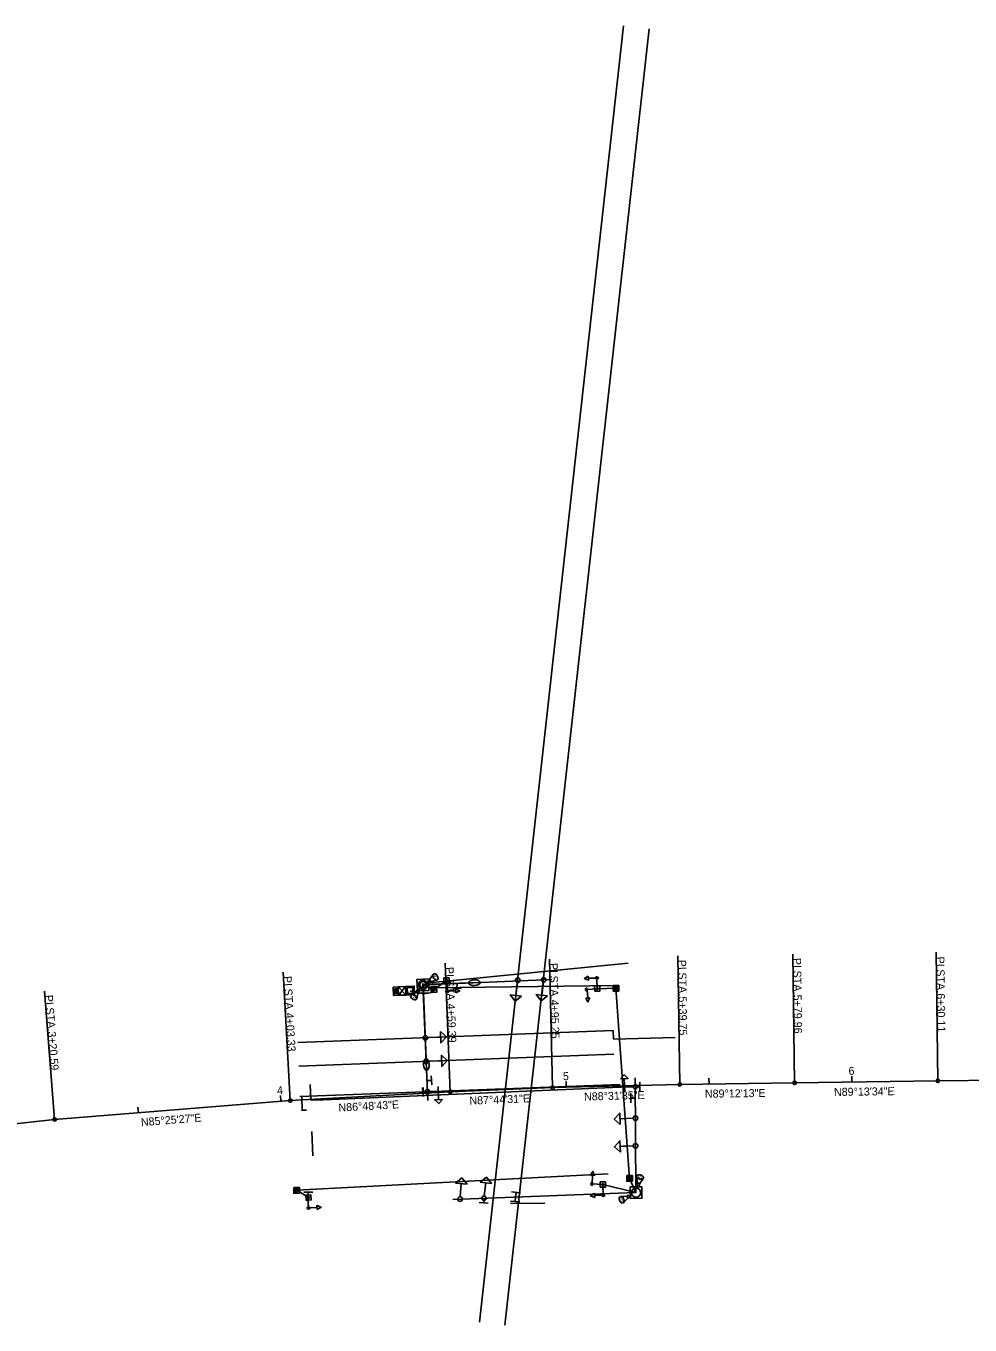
# Model space of a CAD drawing. Extents: x 1369241 to 1370511, y 405823 to 406278.
# Drawn here: x 1369555.1 to 1369885.4, y 405822.9 to 406277.6 of the extents above; entities that cross this region are included whole.
import ezdxf

# ---------------------------------------------------------------- set-up
doc = ezdxf.new("R2010")
doc.units = 0
for name, color, linetype in [('_CIVIL_CONSTRUCTION', 7, 'Continuous'), ('CM_Corridor_Conceptual', 7, 'Continuous'), ('CM_Corridor_Range_Conceptual', 7, 'Continuous'), ('DT_P_Tie', 7, 'Continuous'), ('GE_P_Alignment', 7, 'Continuous'), ('MD_P_ACB_B', 7, 'Continuous'), ('MD_P_ACIC_B', 7, 'Continuous'), ('MD_P_ACSC_T', 7, 'Continuous'), ('MD_P_CSS_B', 7, 'Continuous'), ('MD_P_CURB_BACK_BOT', 7, 'Continuous'), ('MD_P_CURB_BACK_TOP', 7, 'Continuous'), ('MD_P_CURB_FACE_TOP', 7, 'Continuous'), ('PM_P_Crosswalk', 7, 'Continuous'), ('SC_Scratch1', 7, 'Continuous')]:
    doc.layers.add(name, color=color, linetype=linetype)

msp = doc.modelspace()

# ---------------------------------------------------------------- linework, layer by layer
at = {"layer": '_CIVIL_CONSTRUCTION'}
for p, q in [((1369685.39, 405938.97), (1369684.07, 405940.53)), ((1369684.14, 405938.91), (1369685.31, 405940.59)), ((1369688.08, 405938.41), (1369685.28, 405941.28)), ((1369685.42, 405938.28), (1369687.94, 405941.4))]:
    msp.add_line(p, q, dxfattribs=at)
for points in [[(1369691.08, 405938.55), (1369690.94, 405941.54), (1369683.57, 405941.2), (1369683.71, 405938.2)], [(1369685.39, 405938.97), (1369684.14, 405938.91), (1369684.07, 405940.53), (1369685.31, 405940.59)], [(1369688.08, 405938.41), (1369685.42, 405938.28), (1369685.28, 405941.28), (1369687.94, 405941.4)], [(1369691.08, 405938.55), (1369690.94, 405941.54), (1369687.94, 405941.4), (1369688.08, 405938.41)], [(1369690.56, 405939.02), (1369690.46, 405941.02), (1369688.47, 405940.93), (1369688.56, 405938.93)]]:
    msp.add_lwpolyline(points, close=True, dxfattribs=at)
at = {"layer": 'CM_Corridor_Conceptual'}
for p, q in [((1369702.28, 405944.43), (1369702.28, 405944.43)), ((1369727.07, 405942.78), (1369726.53, 405938.22)), ((1369736.14, 405942.93), (1369735.61, 405938.37)), ((1369756.1, 405940.72), (1369756.1, 405940.72)), ((1369755.03, 405939.65), (1369755.03, 405939.65)), ((1369695.61, 405923.5), (1369700.21, 405923.67)), ((1369695.93, 405915.24), (1369700.52, 405915.41)), ((1369764.6, 405904.48), (1369764.42, 405909.18)), ((1369696.37, 405904.61), (1369700.97, 405904.8)), ((1369699.28, 405906.45), (1369699.48, 405901.75)), ((1369767.52, 405906.31), (1369762.92, 405906.13)), ((1369767.56, 405895.29), (1369762.97, 405895.1)), ((1369767.6, 405885.59), (1369763.01, 405885.4)), ((1369707.05, 405867.81), (1369707.41, 405872.39)), ((1369715.46, 405868.12), (1369715.99, 405872.69)), ((1369756.91, 405873.05), (1369756.91, 405873.05)), ((1369757.88, 405872.04), (1369757.88, 405872.04)), ((1369653.67, 405868.6), (1369653.67, 405868.6))]:
    msp.add_line(p, q, dxfattribs=at)
for points in [[(1369751.87, 405944.96), (1369751.91, 405943.56), (1369750.49, 405944.22)], [(1369705.49, 405939.15), (1369705.43, 405940.54), (1369706.86, 405939.9)], [(1369728.52, 405937.99), (1369726.3, 405936.23), (1369724.55, 405938.45)], [(1369737.59, 405938.14), (1369735.37, 405936.38), (1369733.62, 405938.6)], [(1369750.94, 405937.32), (1369752.34, 405937.43), (1369751.74, 405935.98)], [(1369700.13, 405925.67), (1369702.21, 405923.75), (1369700.28, 405921.67)], [(1369700.45, 405917.41), (1369702.52, 405915.49), (1369700.6, 405913.41)], [(1369763.1, 405909.12), (1369764.38, 405910.5), (1369765.76, 405909.22)], [(1369700.8, 405901.81), (1369699.53, 405900.43), (1369698.14, 405901.7)], [(1369763.05, 405893.1), (1369760.97, 405895.02), (1369762.89, 405897.1)], [(1369763.1, 405883.41), (1369761.01, 405885.32), (1369762.93, 405887.4)], [(1369752.66, 405875.34), (1369754.06, 405875.26), (1369753.44, 405876.7)], [(1369705.42, 405872.55), (1369707.57, 405874.38), (1369709.41, 405872.23)], [(1369714.01, 405872.91), (1369716.22, 405874.67), (1369717.98, 405872.45)], [(1369754.1, 405867.54), (1369754.05, 405868.94), (1369752.68, 405868.19)], [(1369656.97, 405863.38), (1369656.89, 405864.78), (1369658.33, 405864.16)]]:
    msp.add_lwpolyline(points, close=True, dxfattribs=at)
for points in [[(1369754.99, 405940.85), (1369754.89, 405944.35), (1369751.89, 405944.26)], [(1369702.33, 405943.23), (1369702.46, 405939.73), (1369705.46, 405939.85)], [(1369754.9, 405940.63), (1369751.41, 405940.37), (1369751.64, 405937.38)], [(1369756.68, 405872.1), (1369753.19, 405872.31), (1369753.36, 405875.3)], [(1369756.95, 405871.85), (1369757.08, 405868.35), (1369754.08, 405868.24)], [(1369653.74, 405867.4), (1369653.94, 405863.91), (1369656.93, 405864.08)]]:
    msp.add_lwpolyline(points, dxfattribs=at)
for centre in [(1369727.16, 405943.58), (1369736.23, 405943.73), (1369694.81, 405923.47), (1369695.13, 405915.21), (1369695.57, 405904.58), (1369768.32, 405906.34), (1369768.36, 405895.33), (1369768.4, 405885.63), (1369706.99, 405867.01), (1369715.37, 405867.32)]:
    msp.add_circle(centre, 0.8, dxfattribs=at)
at = {"layer": 'CM_Corridor_Range_Conceptual'}
for p, q in [((1369694.1, 405939.15), (1369694.05, 405940.75)), ((1369707.49, 405940.72), (1369704.3, 405940.98)), ((1369705.89, 405940.85), (1369706.02, 405942.44)), ((1369705.89, 405940.85), (1369705.89, 405940.85)), ((1369695.7, 405939.2), (1369692.5, 405939.1)), ((1369694.1, 405939.15), (1369694.1, 405939.15)), ((1369696.98, 405908.53), (1369695.38, 405908.46)), ((1369696.92, 405910.13), (1369697.05, 405906.93)), ((1369696.98, 405908.53), (1369696.98, 405908.53)), ((1369694.06, 405902.86), (1369693.81, 405906.05)), ((1369693.94, 405904.45), (1369695.53, 405904.58)), ((1369693.94, 405904.45), (1369693.94, 405904.45)), ((1369766.74, 405900.73), (1369766.73, 405903.93)), ((1369769.92, 405906.34), (1369768.32, 405906.34)), ((1369769.91, 405907.94), (1369769.92, 405904.74)), ((1369769.92, 405906.34), (1369769.92, 405906.34)), ((1369766.73, 405902.33), (1369768.33, 405902.34)), ((1369766.73, 405902.33), (1369766.73, 405902.33)), ((1369652.26, 405869.4), (1369655.46, 405869.47)), ((1369653.86, 405869.44), (1369653.9, 405867.84)), ((1369653.86, 405869.44), (1369653.86, 405869.44)), ((1369715.25, 405865.73), (1369715.38, 405867.32)), ((1369724.98, 405869.48), (1369728.16, 405869.13)), ((1369726.26, 405866.13), (1369726.39, 405867.72)), ((1369726.57, 405869.3), (1369726.39, 405867.71)), ((1369726.57, 405869.3), (1369726.57, 405869.3)), ((1369716.84, 405865.6), (1369713.65, 405865.86)), ((1369715.25, 405865.73), (1369715.25, 405865.73)), ((1369727.86, 405866), (1369724.67, 405866.26)), ((1369726.26, 405866.13), (1369726.26, 405866.13))]:
    msp.add_line(p, q, dxfattribs=at)
at = {"layer": 'DT_P_Tie'}
for p, q in [((1369696.3, 405943.8), (1369697.54, 405945.64)), ((1369697.54, 405945.64), (1369696.3, 405943.8)), ((1369693.03, 405941), (1369692.43, 405940.13)), ((1369695.02, 405942.47), (1369695.89, 405943.07)), ((1369696.3, 405943.8), (1369696.72, 405943.18)), ((1369696.72, 405943.18), (1369698.89, 405943.65)), ((1369696.72, 405943.18), (1369698.89, 405943.65)), ((1369703.02, 405939.87), (1369701.9, 405939.82)), ((1369702.32, 405943.44), (1369702.46, 405939.85)), ((1369751.45, 405939.81), (1369751.37, 405940.93)), ((1369755, 405940.64), (1369751.41, 405940.37)), ((1369754.33, 405944.22), (1369755.45, 405944.25)), ((1369755, 405940.64), (1369754.89, 405944.24)), ((1369691.7, 405939.72), (1369689.85, 405938.5)), ((1369691.7, 405939.72), (1369689.85, 405938.5)), ((1369692.32, 405939.3), (1369691.7, 405939.72)), ((1369692.32, 405939.3), (1369691.83, 405937.14)), ((1369691.83, 405937.14), (1369692.32, 405939.3)), ((1369753.38, 405872.86), (1369753.32, 405871.74)), ((1369756.94, 405872.09), (1369753.35, 405872.3)), ((1369756.94, 405872.09), (1369757.07, 405868.49)), ((1369769.13, 405872.63), (1369768.78, 405874.82)), ((1369768.78, 405874.82), (1369769.13, 405872.63)), ((1369769.09, 405870.78), (1369769.33, 405871.81)), ((1369769.13, 405872.63), (1369769.86, 405872.46)), ((1369769.86, 405872.46), (1369771.12, 405874.28)), ((1369769.86, 405872.46), (1369771.12, 405874.28)), ((1369653.72, 405867.66), (1369653.93, 405864.06)), ((1369756.51, 405868.47), (1369757.63, 405868.51)), ((1369765.39, 405868.05), (1369763.18, 405867.95)), ((1369765.39, 405868.05), (1369763.18, 405867.95)), ((1369765.71, 405867.37), (1369764.18, 405865.77)), ((1369764.18, 405865.77), (1369765.71, 405867.37)), ((1369765.71, 405867.37), (1369765.39, 405868.05)), ((1369767.2, 405868.46), (1369766.23, 405868.02)), ((1369654.49, 405864.1), (1369653.37, 405864.03))]:
    msp.add_line(p, q, dxfattribs=at)
for points in [[(1369692.74, 405939.92), (1369692.12, 405940.34), (1369691.7, 405939.72), (1369692.32, 405939.3)], [(1369695.68, 405943.38), (1369696.1, 405942.76), (1369696.72, 405943.18), (1369696.3, 405943.8)], [(1369768.96, 405871.9), (1369769.69, 405871.73), (1369769.86, 405872.46), (1369769.13, 405872.63)], [(1369766.39, 405867.68), (1369766.08, 405868.37), (1369765.39, 405868.05), (1369765.71, 405867.37)]]:
    msp.add_lwpolyline(points, close=True, dxfattribs=at)
for points in [[(1369692.74, 405939.92), (1369692.12, 405940.34), (1369691.7, 405939.72), (1369692.32, 405939.3), (1369692.74, 405939.92)], [(1369695.68, 405943.38), (1369696.1, 405942.76), (1369696.72, 405943.18), (1369696.3, 405943.8), (1369695.68, 405943.38)], [(1369768.96, 405871.9), (1369769.69, 405871.73), (1369769.86, 405872.46), (1369769.13, 405872.63), (1369768.96, 405871.9)], [(1369766.39, 405867.68), (1369766.08, 405868.37), (1369765.39, 405868.05), (1369765.71, 405867.37), (1369766.39, 405867.68)]]:
    msp.add_lwpolyline(points, dxfattribs=at)
for centre, start, end in [((1369754.89, 405944.24), 1.7331, 181.7327), ((1369702.46, 405939.85), 182.1814, 2.181), ((1369751.41, 405940.37), 94.3061, 274.3057), ((1369753.35, 405872.3), 86.695, 266.6946), ((1369757.07, 405868.49), 182.0638, 2.0634), ((1369653.93, 405864.06), 183.273, 3.2727)]:
    msp.add_arc(centre, 0.56, start, end, dxfattribs=at)
for centre, major_axis in [((1369698.37, 405944.75), (0.7, -1.02)), ((1369690.73, 405937.66), (-1.02, 0.7)), ((1369769.99, 405874.73), (1.21, -0.28)), ((1369763.51, 405866.78), (-0.51, 1.13))]:
    msp.add_ellipse(centre, major_axis=major_axis, ratio=0.621318, dxfattribs=at)
for centre, major_axis in [((1369698.37, 405944.75), (0.7, -1.02)), ((1369690.73, 405937.66), (-1.02, 0.7)), ((1369769.99, 405874.73), (1.21, -0.28)), ((1369763.51, 405866.78), (-0.51, 1.13))]:
    msp.add_ellipse(centre, major_axis=major_axis, ratio=0.621318, start_param=3.386213, end_param=6.038231, dxfattribs=at)
at = {"layer": 'GE_P_Alignment'}
for points in [[(1369701.41, 405942.6), (1369703.21, 405942.65), (1369703.15, 405944.45), (1369701.35, 405944.4)], [(1369692.09, 405939.85), (1369696.09, 405940.05), (1369695.89, 405944.04), (1369691.9, 405943.85)], [(1369754.13, 405939.71), (1369755.93, 405939.79), (1369755.85, 405941.59), (1369754.05, 405941.5)], [(1369756.04, 405871.19), (1369757.84, 405871.19), (1369757.84, 405872.99), (1369756.04, 405872.99)], [(1369653.12, 405866.56), (1369654.91, 405866.73), (1369654.74, 405868.52), (1369652.95, 405868.35)], [(1369766.62, 405867.23), (1369770.62, 405867.3), (1369770.55, 405871.29), (1369766.55, 405871.23)]]:
    msp.add_lwpolyline(points, close=True, dxfattribs=at)
for centre, radius in [((1369702.28, 405943.52), 0.3), ((1369754.99, 405940.65), 0.3), ((1369756.94, 405872.09), 0.3), ((1369653.93, 405867.54), 0.3), ((1369768.59, 405869.26), 1.6)]:
    msp.add_circle(centre, radius, dxfattribs=at)
msp.add_ellipse((1369693.99, 405941.95), major_axis=(1.6, 0.08), ratio=0.999752, dxfattribs=at)
at = {"layer": 'MD_P_ACB_B'}
for p, q in [((1369697.81, 405940.4), (1369697.81, 405940.4)), ((1369761.51, 405940.79), (1369761.51, 405940.79)), ((1369766.29, 405874.24), (1369766.29, 405874.24)), ((1369649.75, 405870.07), (1369649.75, 405870.07))]:
    msp.add_line(p, q, dxfattribs=at)
for points in [[(1369696.76, 405941.34), (1369698.75, 405941.46), (1369698.87, 405939.46), (1369696.87, 405939.34)], [(1369760.51, 405941.79), (1369762.51, 405941.79), (1369762.51, 405939.79), (1369760.51, 405939.79)], [(1369765.29, 405875.24), (1369767.29, 405875.24), (1369767.29, 405873.24), (1369765.29, 405873.24)], [(1369648.75, 405871.07), (1369650.75, 405871.07), (1369650.75, 405869.07), (1369648.75, 405869.07)]]:
    msp.add_lwpolyline(points, close=True, dxfattribs=at)
for points in [[(1369696.87, 405941.01), (1369697.7, 405941.06)], [(1369697.29, 405941.03), (1369697.37, 405939.7)], [(1369697.93, 405939.74), (1369697.85, 405941.07), (1369698.35, 405941.1), (1369698.4, 405941.09), (1369698.48, 405941.07), (1369698.51, 405941.05), (1369698.54, 405941.04), (1369698.59, 405940.99), (1369698.62, 405940.94), (1369698.65, 405940.85), (1369698.66, 405940.73), (1369698.65, 405940.68), (1369698.63, 405940.62), (1369698.59, 405940.54), (1369698.55, 405940.51), (1369698.52, 405940.49), (1369698.5, 405940.48), (1369698.47, 405940.46), (1369698.38, 405940.45), (1369697.89, 405940.42)], [(1369698.38, 405940.45), (1369698.71, 405939.78)], [(1369760.6, 405941.45), (1369761.43, 405941.45)], [(1369761.02, 405941.45), (1369761.02, 405940.12)], [(1369761.58, 405940.12), (1369761.58, 405941.45), (1369762.09, 405941.45), (1369762.14, 405941.44), (1369762.21, 405941.42), (1369762.24, 405941.4), (1369762.28, 405941.38), (1369762.32, 405941.33), (1369762.35, 405941.27), (1369762.37, 405941.19), (1369762.37, 405941.06), (1369762.36, 405941.02), (1369762.34, 405940.96), (1369762.3, 405940.89), (1369762.25, 405940.85), (1369762.22, 405940.83), (1369762.2, 405940.82), (1369762.17, 405940.81), (1369762.08, 405940.8), (1369761.58, 405940.8)], [(1369762.08, 405940.8), (1369762.37, 405940.12)], [(1369765.38, 405874.9), (1369766.21, 405874.9)], [(1369765.8, 405874.9), (1369765.8, 405873.57)], [(1369766.36, 405873.57), (1369766.36, 405874.9), (1369766.87, 405874.9), (1369766.92, 405874.89), (1369766.99, 405874.87), (1369767.02, 405874.85), (1369767.05, 405874.83), (1369767.1, 405874.78), (1369767.13, 405874.72), (1369767.15, 405874.64), (1369767.15, 405874.51), (1369767.14, 405874.47), (1369767.12, 405874.41), (1369767.08, 405874.34), (1369767.03, 405874.3), (1369767, 405874.28), (1369766.98, 405874.27), (1369766.95, 405874.26), (1369766.85, 405874.25), (1369766.36, 405874.25)], [(1369766.85, 405874.25), (1369767.15, 405873.57)], [(1369648.85, 405870.74), (1369649.68, 405870.74)], [(1369649.27, 405870.74), (1369649.27, 405869.41)], [(1369649.83, 405869.41), (1369649.83, 405870.74), (1369650.33, 405870.74), (1369650.39, 405870.73), (1369650.46, 405870.71), (1369650.49, 405870.69), (1369650.52, 405870.67), (1369650.56, 405870.61), (1369650.6, 405870.56), (1369650.62, 405870.48), (1369650.62, 405870.35), (1369650.61, 405870.31), (1369650.59, 405870.25), (1369650.54, 405870.17), (1369650.5, 405870.14), (1369650.47, 405870.12), (1369650.45, 405870.11), (1369650.42, 405870.1), (1369650.32, 405870.09), (1369649.83, 405870.09)], [(1369650.32, 405870.09), (1369650.62, 405869.41)]]:
    msp.add_lwpolyline(points, dxfattribs=at)
at = {"layer": 'MD_P_ACIC_B'}
for p, q in [((1369693.99, 405942.47), (1369695.7, 405901.5)), ((1369697.81, 405940.4), (1369694.03, 405942.06)), ((1369761.54, 405941.71), (1369697.68, 405940.95)), ((1369702.32, 405943.48), (1369697.81, 405940.4)), ((1369761.51, 405940.79), (1369755, 405940.64)), ((1369761.51, 405940.79), (1369766.29, 405874.24)), ((1369758.79, 405875.8), (1369649.83, 405870.08)), ((1369768.52, 405869.25), (1369756.94, 405872.09)), ((1369766.29, 405874.24), (1369768.52, 405869.25)), ((1369649.83, 405870.08), (1369653.93, 405867.54))]:
    msp.add_line(p, q, dxfattribs=at)
msp.add_arc((1369693.98, 405949.72), 10.77, 245.4119, 291.0837, dxfattribs=at)
at = {"layer": 'MD_P_ACSC_T'}
for p, q in [((1369694.01, 405942.06), (1369709.99, 405942.66)), ((1369694.01, 405942.07), (1369695.09, 405916.09))]:
    msp.add_line(p, q, dxfattribs=at)
for centre in [(1369694.01, 405942.07), (1369694.01, 405942.06)]:
    msp.add_circle(centre, 1.1, dxfattribs=at)
for centre, major_axis in [((1369711.99, 405942.73), (2, 0.08)), ((1369695.17, 405914.09), (0.08, -2))]:
    msp.add_ellipse(centre, major_axis=major_axis, ratio=0.5, dxfattribs=at)
at = {"layer": 'MD_P_CSS_B'}
for p, q in [((1369744.13, 405906.12), (1369744.08, 405908.12)), ((1369794.12, 405907.28), (1369794.09, 405909.28)), ((1369824.07, 405907.7), (1369874.22, 405908.38)), ((1369844.11, 405907.97), (1369844.09, 405909.97)), ((1369874.22, 405908.38), (1369958.19, 405909.51)), ((1369647.58, 405901.47), (1369703.55, 405904.59)), ((1369694.18, 405904.06), (1369694.06, 405906.06)), ((1369703.55, 405904.59), (1369739.38, 405906)), ((1369739.38, 405906), (1369783.87, 405907.14)), ((1369783.87, 405907.14), (1369824.07, 405907.7)), ((1369565.1, 405894.87), (1369647.58, 405901.47)), ((1369594.42, 405897.21), (1369594.26, 405899.21)), ((1369644.26, 405901.2), (1369644.1, 405903.2)), ((1369493.58, 405887.19), (1369565.1, 405894.87))]:
    msp.add_line(p, q, dxfattribs=at)
at = {"layer": 'MD_P_CURB_BACK_BOT'}
for p, q in [((1369713.74, 405823.92), (1369764.23, 406277.56)), ((1369722.69, 405822.93), (1369773.18, 406276.56)), ((1369760.57, 405925.96), (1369650.23, 405921.77)), ((1369760.66, 405922.96), (1369760.57, 405925.96)), ((1369782.24, 405923.55), (1369760.66, 405922.94)), ((1369760.81, 405917.7), (1369650.54, 405913.51)), ((1369762.99, 405907.16), (1369650.95, 405902.9)), ((1369656.47, 405901.66), (1369765.79, 405906.23)), ((1369763.96, 405885.47), (1369765.07, 405885.47)), ((1369655.32, 405885.08), (1369655.41, 405882.08)), ((1369736.59, 405865.56), (1369724.59, 405865.44))]:
    msp.add_line(p, q, dxfattribs=at)
at = {"layer": 'MD_P_CURB_BACK_TOP'}
for p, q in [((1369651.58, 405902.91), (1369651.77, 405897.91)), ((1369651.81, 405898.11), (1369653.23, 405898.17))]:
    msp.add_line(p, q, dxfattribs=at)
at = {"layer": 'MD_P_CURB_FACE_TOP'}
msp.add_line((1369765.82, 405949.51), (1369695.07, 405942.51), dxfattribs=at)
at = {"layer": 'PM_P_Crosswalk'}
for p, q in [((1369703.55, 405904.59), (1369701.78, 405949.55)), ((1369739.38, 405906), (1369738.23, 405950.98)), ((1369783.87, 405907.14), (1369783.24, 405952.14)), ((1369824.07, 405907.7), (1369823.47, 405952.7)), ((1369874.22, 405908.38), (1369873.61, 405953.37)), ((1369647.58, 405901.47), (1369645.08, 405946.4)), ((1369694.01, 405942.06), (1369713.99, 405942.83)), ((1369565.1, 405894.87), (1369561.51, 405939.72)), ((1369654.55, 405907.07), (1369654.74, 405901.6)), ((1369654.74, 405901.6), (1369658.11, 405901.71)), ((1369655.32, 405885.08), (1369655.12, 405890.6))]:
    msp.add_line(p, q, dxfattribs=at)
for centre in [(1369824.07, 405907.7), (1369874.22, 405908.38), (1369703.55, 405904.59), (1369739.38, 405906), (1369783.87, 405907.14), (1369647.58, 405901.47), (1369565.1, 405894.87)]:
    msp.add_circle(centre, 0.6, dxfattribs=at)
at = {"layer": 'SC_Scratch1'}
for p, q in [((1369739.13, 405943.88), (1369695.07, 405941.99)), ((1369768.52, 405869.16), (1369768.3, 405909.38)), ((1369704.5, 405866.91), (1369768.52, 405869.25))]:
    msp.add_line(p, q, dxfattribs=at)

# ---------------------------------------------------------------- texts
at = {"layer": 'DT_P_Tie'}
for rotation, p in [(34.2934, (1369698.31, 405943.86)), (235.4894, (1369690.47, 405938.51)), (77.2013, (1369770.55, 405874.04)), (204.5251, (1369763.72, 405867.65))]:
    msp.add_text('S', height=1.4, rotation=rotation, dxfattribs=at).set_placement(p)
at = {"layer": 'MD_P_CSS_B'}
for s, rotation, p in [('6', 0.7739, (1369842.96, 405910.46)), ('5', 1.4737, (1369743, 405908.59)), ('4', 4.5757, (1369643.03, 405903.61))]:
    msp.add_text(s, height=2.8, rotation=rotation, dxfattribs=at).set_placement(p)
at = {"layer": 'PM_P_Crosswalk'}
for s, rotation, p in [('PI', 271.4737, (1369738.31, 405949.6)), ('PI', 270.7963, (1369783.3, 405950.76)), ('PI', 270.7739, (1369823.53, 405951.37)), ('PI', 270.7739, (1369873.67, 405951.84)), ('PI', 273.1881, (1369645.2, 405944.99)), ('PI', 272.258, (1369701.88, 405948.18)), (' STA. ', 271.4737, (1369738.39, 405946.21)), (' STA. ', 270.7963, (1369783.35, 405947.36)), (' STA. ', 270.7739, (1369823.57, 405947.98)), (' STA. ', 270.7739, (1369873.72, 405948.45)), (' STA. ', 273.1881, (1369645.39, 405941.6)), (' STA. ', 272.258, (1369702.01, 405944.8)), ('PI', 274.5757, (1369561.66, 405938.36)), ('4+59.39', 272.258, (1369702.38, 405935.35)), ('4+95.25', 271.4737, (1369738.64, 405936.76)), ('5+39.75', 270.7963, (1369783.48, 405937.91)), ('5+79.96', 270.7739, (1369823.7, 405938.53)), ('6+30.11', 270.7739, (1369873.85, 405939)), (' STA. ', 274.5757, (1369561.93, 405934.98)), ('4+03.33', 273.1881, (1369645.91, 405932.16)), ('3+20.59', 274.5757, (1369562.69, 405925.56)), ('N87°44\'31"E', 2.258, (1369710.3, 405900.05)), ('N88°31\'35"E', 1.4737, (1369750.39, 405901.48)), ('N89°12\'13"E', 0.7963, (1369792.68, 405902.46)), ('N89°13\'34"E', 0.7739, (1369837.85, 405903.09)), ('N86°48\'43"E', 3.1881, (1369664.49, 405897.6)), ('N85°25\'27"E', 4.5757, (1369595.4, 405892.48))]:
    msp.add_text(s, height=2.8, rotation=rotation, dxfattribs=at).set_placement(p)

doc.saveas('drawing.dxf')
